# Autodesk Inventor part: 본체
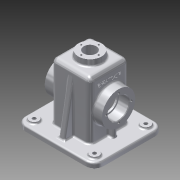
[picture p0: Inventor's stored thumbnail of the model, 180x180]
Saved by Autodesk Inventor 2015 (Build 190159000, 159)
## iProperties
Created: 2016-02
Part Number: 본체
Material: 알루미늄 6061
Document SubType Name: Modeling
Designer: Administrator
Density: 2.7 g/cm^3
Appearance: 알루미늄 - 평지
Mass: 783.577 g
Surface Area: 892.209 cm^2
Volume: 290.214 cm^3
Author: Administrator
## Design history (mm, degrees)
sketch "스케치1"
  geometry: C1 r 27.5 at (0, 0); 1 further point
  constraints: 1 centre point, 1 coincident
  dimensions: "d0" = 55 diameter of C1
extrude "돌출1" new body sketch "스케치1" stored distance "d1" = 95; taper "d2" = 0 deg
node "작업 평면1"
sketch "스케치2"
  geometry: L1 (-65, -57.5)-(65, -57.5); L2 (65, -57.5)-(65, 57.5); L3 (65, 57.5)-(-65, 57.5); L4 (-65, 57.5)-(-65, -57.5); L5 (-65, -57.5)-(65, 57.5); L6 (65, -57.5)-(-65, 57.5); 1 further point
  constraints: 12 end point, 2 midpoint, 2 parallel, 1 horizontal, 1 perpendicular
  dimensions: "d4" = 115 distance between parallel lines of L1 L3; "d5" = 130 distance between parallel lines of L4 L2
extrude "돌출2" join sketch "스케치2" distance "d6" = 8; taper "d7" = 0 deg
sketch "스케치3"
  geometry: L1 (65, 57.5)-(-65, 57.5) reference; L2 (-65, 57.5)-(-65, -57.5) reference; C1 r 7.5 at (-50, 42.5); C2 r 7.5 at (50, 42.5); C3 r 7.5 at (-50, -42.5); C4 r 7.5 at (50, -42.5); 1 further point
  constraints: 4 centre point, 1 horizontal, 1 vertical, 6 other
  dimensions: "d8" = 15 diameter of C1; "d11" = 100 distance of C1.centre C2.centre; "d14" = 85 distance of C1.centre C3.centre; "d17" = 50 horizontal distance of C1.centre point (0, 0); "d18" = 42.5 vertical distance of point (0, 0) C2.centre
extrude "돌출3" join sketch "스케치3" distance "d19" = 3; taper "d20" = 0 deg
fillet "모깎기1" dims "d21" = 15
sketch "스케치4"
  geometry: L1 (-32.5, -50)-(32.5, -50); L2 (32.5, -50)-(32.5, 50); L3 (32.5, 50)-(-32.5, 50); L4 (-32.5, 50)-(-32.5, -50); L5 (-32.5, -50)-(32.5, 50); L6 (32.5, -50)-(-32.5, 50); L7 (50, -53)-(-50, -53) reference; 1 further point
  constraints: 12 end point, 2 midpoint, 2 parallel, 1 horizontal, 1 perpendicular
  dimensions: "d22" = 103 distance between parallel lines of L7 L3; "d23" = 65 distance between parallel lines of L4 L2
extrude "돌출4" join sketch "스케치4" stored distance "d24" = 65; taper "d25" = 0 deg
node "작업 평면2"
sketch "스케치9"
  geometry: L1 (60, -52.5)-(-60, -52.5); L2 (-60, -52.5)-(-60, 52.5); L3 (-60, 52.5)-(60, 52.5); L4 (60, 52.5)-(60, -52.5); L5 (60, -52.5)-(-60, 52.5); L6 (-60, -52.5)-(60, 52.5); L7 (-65, 42.5)-(-65, -42.5) reference; L8 (50, 57.5)-(-50, 57.5) reference; 1 further point
  constraints: 12 end point, 2 midpoint, 2 parallel, 1 horizontal, 1 perpendicular
  dimensions: "d43" = 5 distance between parallel lines of L7 L2; "d44" = 5 distance between parallel lines of L8 L3
extrude "돌출7" join sketch "스케치9" distance "d45" = 2; taper "d46" = 0 deg
sketch "스케치10"
  geometry: L1 (17.5, 75)-(82.5, 75) reference; L2 (82.5, 75)-(82.5, 10) reference; L3 (82.5, 10)-(17.5, 10) reference; L4 (17.5, 10)-(17.5, 75) reference; L5 (-15, 85)-(-15, 0) reference; L6 (0, -15)-(100, -15) reference; L7 (115, 0)-(115, 85) reference; L8 (100, 100)-(0, 100) reference; C1 r 7.5 at (0, 0) reference; C2 r 7.5 at (0, 85) reference; C3 r 7.5 at (100, 85) reference; C4 r 7.5 at (100, 0) reference; C5 r 7.5 at (100, 0) reference; A1 r 15 centre (0, 85) between (0, 100) and (-15, 85) reference; A2 r 15 centre (0, 0) between (-15, 0) and (0, -15) reference; A3 r 15 centre (100, 0) between (100, -15) and (115, 0) reference; A4 r 15 centre (100, 85) between (115, 85) and (100, 100) reference; 5 further points
  constraints: 4 coincident
hole "구멍3" sketch "스케치10" at (0, 0), (100, 0), (100, 85), (0, 85) diameter "d57" = 6; stored, may be unused: countersink angle "d61" = 90 deg, drill point angle "d63" = 118 deg; dims "d58" = 6, "d59" = 4, "d60" = 2, "d62" = 8
sketch "스케치13"
  geometry: C1 r 20 at (32.5, 32.5); 1 further point
  constraints: 1 centre point, 1 coincident
  dimensions: "d66" = 40 diameter of C1
extrude "돌출8" join sketch "스케치13" distance "d67" = 10; taper "d68" = 0 deg
feature "면 기울기2" dims angle "d69" = 5 deg
hole "구멍4" diameter "d72" = 35; stored, may be unused: countersink angle "d76" = 90 deg, drill point angle "d78" = 0 deg; dims "d70" = 10, "d71" = 10, "d73" = 6, "d74" = 4, "d75" = 2, "d77" = 17
hole "구멍5" diameter "d81" = 30; stored, may be unused: countersink angle "d85" = 90 deg, drill point angle "d87" = 0 deg; dims "d79" = 10, "d80" = 10, "d82" = 6, "d83" = 4, "d84" = 2, "d86" = 17
hole "구멍6" diameter "d90" = 35; stored, may be unused: countersink angle "d94" = 90 deg, drill point angle "d96" = 0 deg; dims "d88" = 10, "d89" = 10, "d91" = 6, "d92" = 4, "d93" = 2, "d95" = 17
sketch "스케치15"
  geometry: L1 (-32.5, 27.5)-(-32.5, 50) reference; L2 (-32.5, 50)-(-20, 50) reference; L3 (-20, 50)-(-19.125, 60) reference; L4 (-19.125, 60)-(19.125, 60) reference; L5 (19.125, 60)-(20, 50) reference; L6 (20, 50)-(32.5, 50) reference; L7 (32.5, 50)-(32.5, 27.5) reference; L8 (32.5, 27.5)-(47.5, 27.5) reference; L9 (47.5, 27.5)-(47.5, 17.5) reference; L10 (47.5, 17.5)-(30.5, 17.5) reference; L11 (30.5, 17.5)-(30.5, 15) reference; L12 (30.5, 15)-(-30.5, 15) reference; L13 (-30.5, 15)-(-30.5, 17.5) reference; L14 (-30.5, 17.5)-(-47.5, 17.5) reference; L15 (-47.5, 17.5)-(-47.5, 27.5) reference; L16 (-47.5, 27.5)-(-32.5, 27.5) reference; L17 (-65, -53)-(-65, -45) reference; L18 (-65, -45)-(-32.5, -45) reference; L19 (-32.5, -45)-(-32.5, -27.5) reference; L20 (-32.5, -27.5)-(-47.5, -27.5) reference; L21 (-47.5, -27.5)-(-47.5, -17.5) reference; L22 (-47.5, -17.5)-(-30.5, -17.5) reference; L23 (-30.5, -17.5)-(-30.5, -15) reference; L24 (-30.5, -15)-(30.5, -15) reference; L25 (30.5, -15)-(30.5, -17.5) reference; L26 (30.5, -17.5)-(47.5, -17.5) reference; L27 (47.5, -17.5)-(47.5, -27.5) reference; L28 (47.5, -27.5)-(32.5, -27.5) reference; L29 (32.5, -27.5)-(32.5, -45) reference; L30 (32.5, -45)-(65, -45) reference; L31 (65, -45)-(65, -53) reference; L32 (65, -53)-(60, -53) reference; L33 (60, -53)-(60, -55) reference; L34 (60, -55)-(-60, -55) reference; L35 (-60, -55)-(-60, -53) reference; L36 (-60, -53)-(-65, -53) reference; L37 (27.5, 45)-(-27.5, 45); L38 (-27.5, 45)-(-27.5, -55); L39 (-27.5, -55)-(27.5, -55); L40 (27.5, -55)-(27.5, 45); 1 further point
  constraints: 8 end point, 2 parallel, 1 horizontal, 1 perpendicular
  dimensions: "d104" = 15 distance between parallel lines of L4 L37; "d105" = 5 distance between parallel lines of L1 L38; "d106" = 0 distance between parallel lines of L34 L39; "d107" = 5 distance between parallel lines of L7 L40
extrude "돌출9" cut sketch "스케치15" stored distance "d101" = 55; taper "d102" = 0 deg
fillet "모깎기3" dims "d108" = 8
fillet "모깎기4" dims "d109" = 8
fillet "모깎기5" dims "d110" = 3
chamfer "모따기1" distance "d111" = 1; stored, may be unused: second distance "d112" = 2, angle "d113" = 45 deg
fillet "모깎기6" dims "d114" = 0.3
sketch "스케치16" dims "d115" = 42
  geometry: C1 r 27.5 at (0, 0) reference; C2 r 18.5 at (0, 0) reference; 5 further points
  constraints: 2 vertical alignment, 1 coincident, 7 other
  dimensions: "d118" = 360 deg dimension on C1.centre point (0, 21) (derived)
hole "구멍7" sketch "스케치16" at (0, 21), (-21, 0), (0, -21), (21, 0) diameter "d120" = 3.242; stored, may be unused: countersink angle "d124" = 90 deg, drill point angle "d126" = 118 deg; dims "d121" = 8, "d122" = 4, "d123" = 2, "d125" = 10
sketch "스케치17" dims "d127" = 42
  geometry: C1 r 27.5 at (0, 0) reference; C2 r 18.5 at (0, 0) reference; 5 further points
  constraints: 2 vertical alignment, 1 coincident, 7 other
  dimensions: "d130" = 360 deg dimension on C1.centre point (0, 21) (derived)
hole "구멍8" sketch "스케치17" at (0, 21), (-21, 0), (0, -21), (21, 0) diameter "d132" = 3.242; stored, may be unused: countersink angle "d136" = 90 deg, drill point angle "d138" = 118 deg; dims "d133" = 8, "d134" = 4, "d135" = 2, "d137" = 10
sketch "스케치18"
  geometry: L1 (-58.808, -47.5)-(-11.41, -47.5); L2 (-45, -57.5)-(-53, -57.5) reference; L3 (-45, -42.5)-(-45, -57.5) reference; L4 (-45, -47.5)-(40.069, -32.5); L5 (42, -32.5)-(-45, -32.5) reference; L6 (40.069, -32.5)-(-45, -32.5); L7 (-45, -32.5)-(-45, -47.5); 1 further point
  constraints: 8 end point, 3 point on line, 2 collinear, 1 horizontal
  dimensions: "d141" = 10 distance between parallel lines of L2 L1; "d142" = 10 deg angle of L1 L4
extrude "돌출10" join sketch "스케치18" stored distance "d143" = 10; taper "d144" = 0 deg
fillet "모깎기9" dims "d147" = 3
sketch "스케치19"
  geometry: C1 r 19.125 at (0, 0) reference; C2 r 10.5 at (0, 0)
  constraints: 1 centre point, 1 coincident
  dimensions: "d148" = 21 diameter of C2
extrude "돌출11" cut sketch "스케치19" stored distance "d149" = 10; taper "d150" = 0 deg
fillet "모깎기10" dims "d151" = 3
fillet "모깎기11" dims "d152" = 3
fillet "모깎기12" dims "d153" = 3
fillet "모깎기13" dims "d154" = 3
sketch "스케치20" dims "d155" = 29
  geometry: C1 r 10.5 at (0, 0) reference; C2 r 19.125 at (0, 0) reference; 5 further points
  constraints: 2 horizontal alignment, 1 coincident, 7 other
  dimensions: "d158" = 360 deg dimension on C1.centre point (-14.5, 0) (derived)
hole "구멍9" sketch "스케치20" at (-14.5, 0), (0, -14.5), (14.5, 0), (0, 14.5) diameter "d160" = 2.459; stored, may be unused: countersink angle "d164" = 90 deg, drill point angle "d166" = 118 deg; dims "d161" = 7, "d162" = 4, "d163" = 2, "d165" = 9
fillet "모깎기14" dims "d167" = 3
sketch "스케치21"
  geometry: L1 (42.5, -25)-(42.5, -55); L2 (27.5, 45)-(27.5, -55) reference; L3 (42.5, -55)-(27.5, -55); L4 (27.5, -25)-(27.5, -55); L5 (-60, -55)-(60, -55) reference; L6 (27.5, -25)-(42.5, -25); 1 further point
  constraints: 8 end point, 2 perpendicular, 2 point on line, 1 collinear, 1 vertical
  dimensions: "d169" = 15 distance between parallel lines of L1 L2; "d170" = 0 distance between parallel lines of L5 L3; "d171" = 30 distance between parallel lines of L3 L6
extrude "돌출12" join sketch "스케치21" stored distance "d172" = 6; taper "d173" = 0 deg
fillet "모깎기15" dims "d174" = 3
fillet "모깎기16" dims "d175" = 3
fillet "모깎기17" dims "d176" = 3
fillet "모깎기18" dims "d177" = 3
node "작업 평면3"
sketch "스케치22"
  geometry: L1 (60, -19.125)-(60, 19.125) reference; 2 further points
  constraints: 1 horizontal alignment, 1 other
  dimensions: "d179" = 26 distance from line of L1 point (34, 0)
feature "엠보싱1" sketch "스케치22" dims "d180" = 0.5, "d181" = 0
fillet "모깎기19" dims "d182" = 3
node "솔리드1"
mirror "대칭1"
mirror "대칭2"
node "투영된 루프4"
node "절단 모서리 투영1"
other parameters: "d3" = -53, "d42" = -55
